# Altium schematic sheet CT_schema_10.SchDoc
size 388 x 385 mm
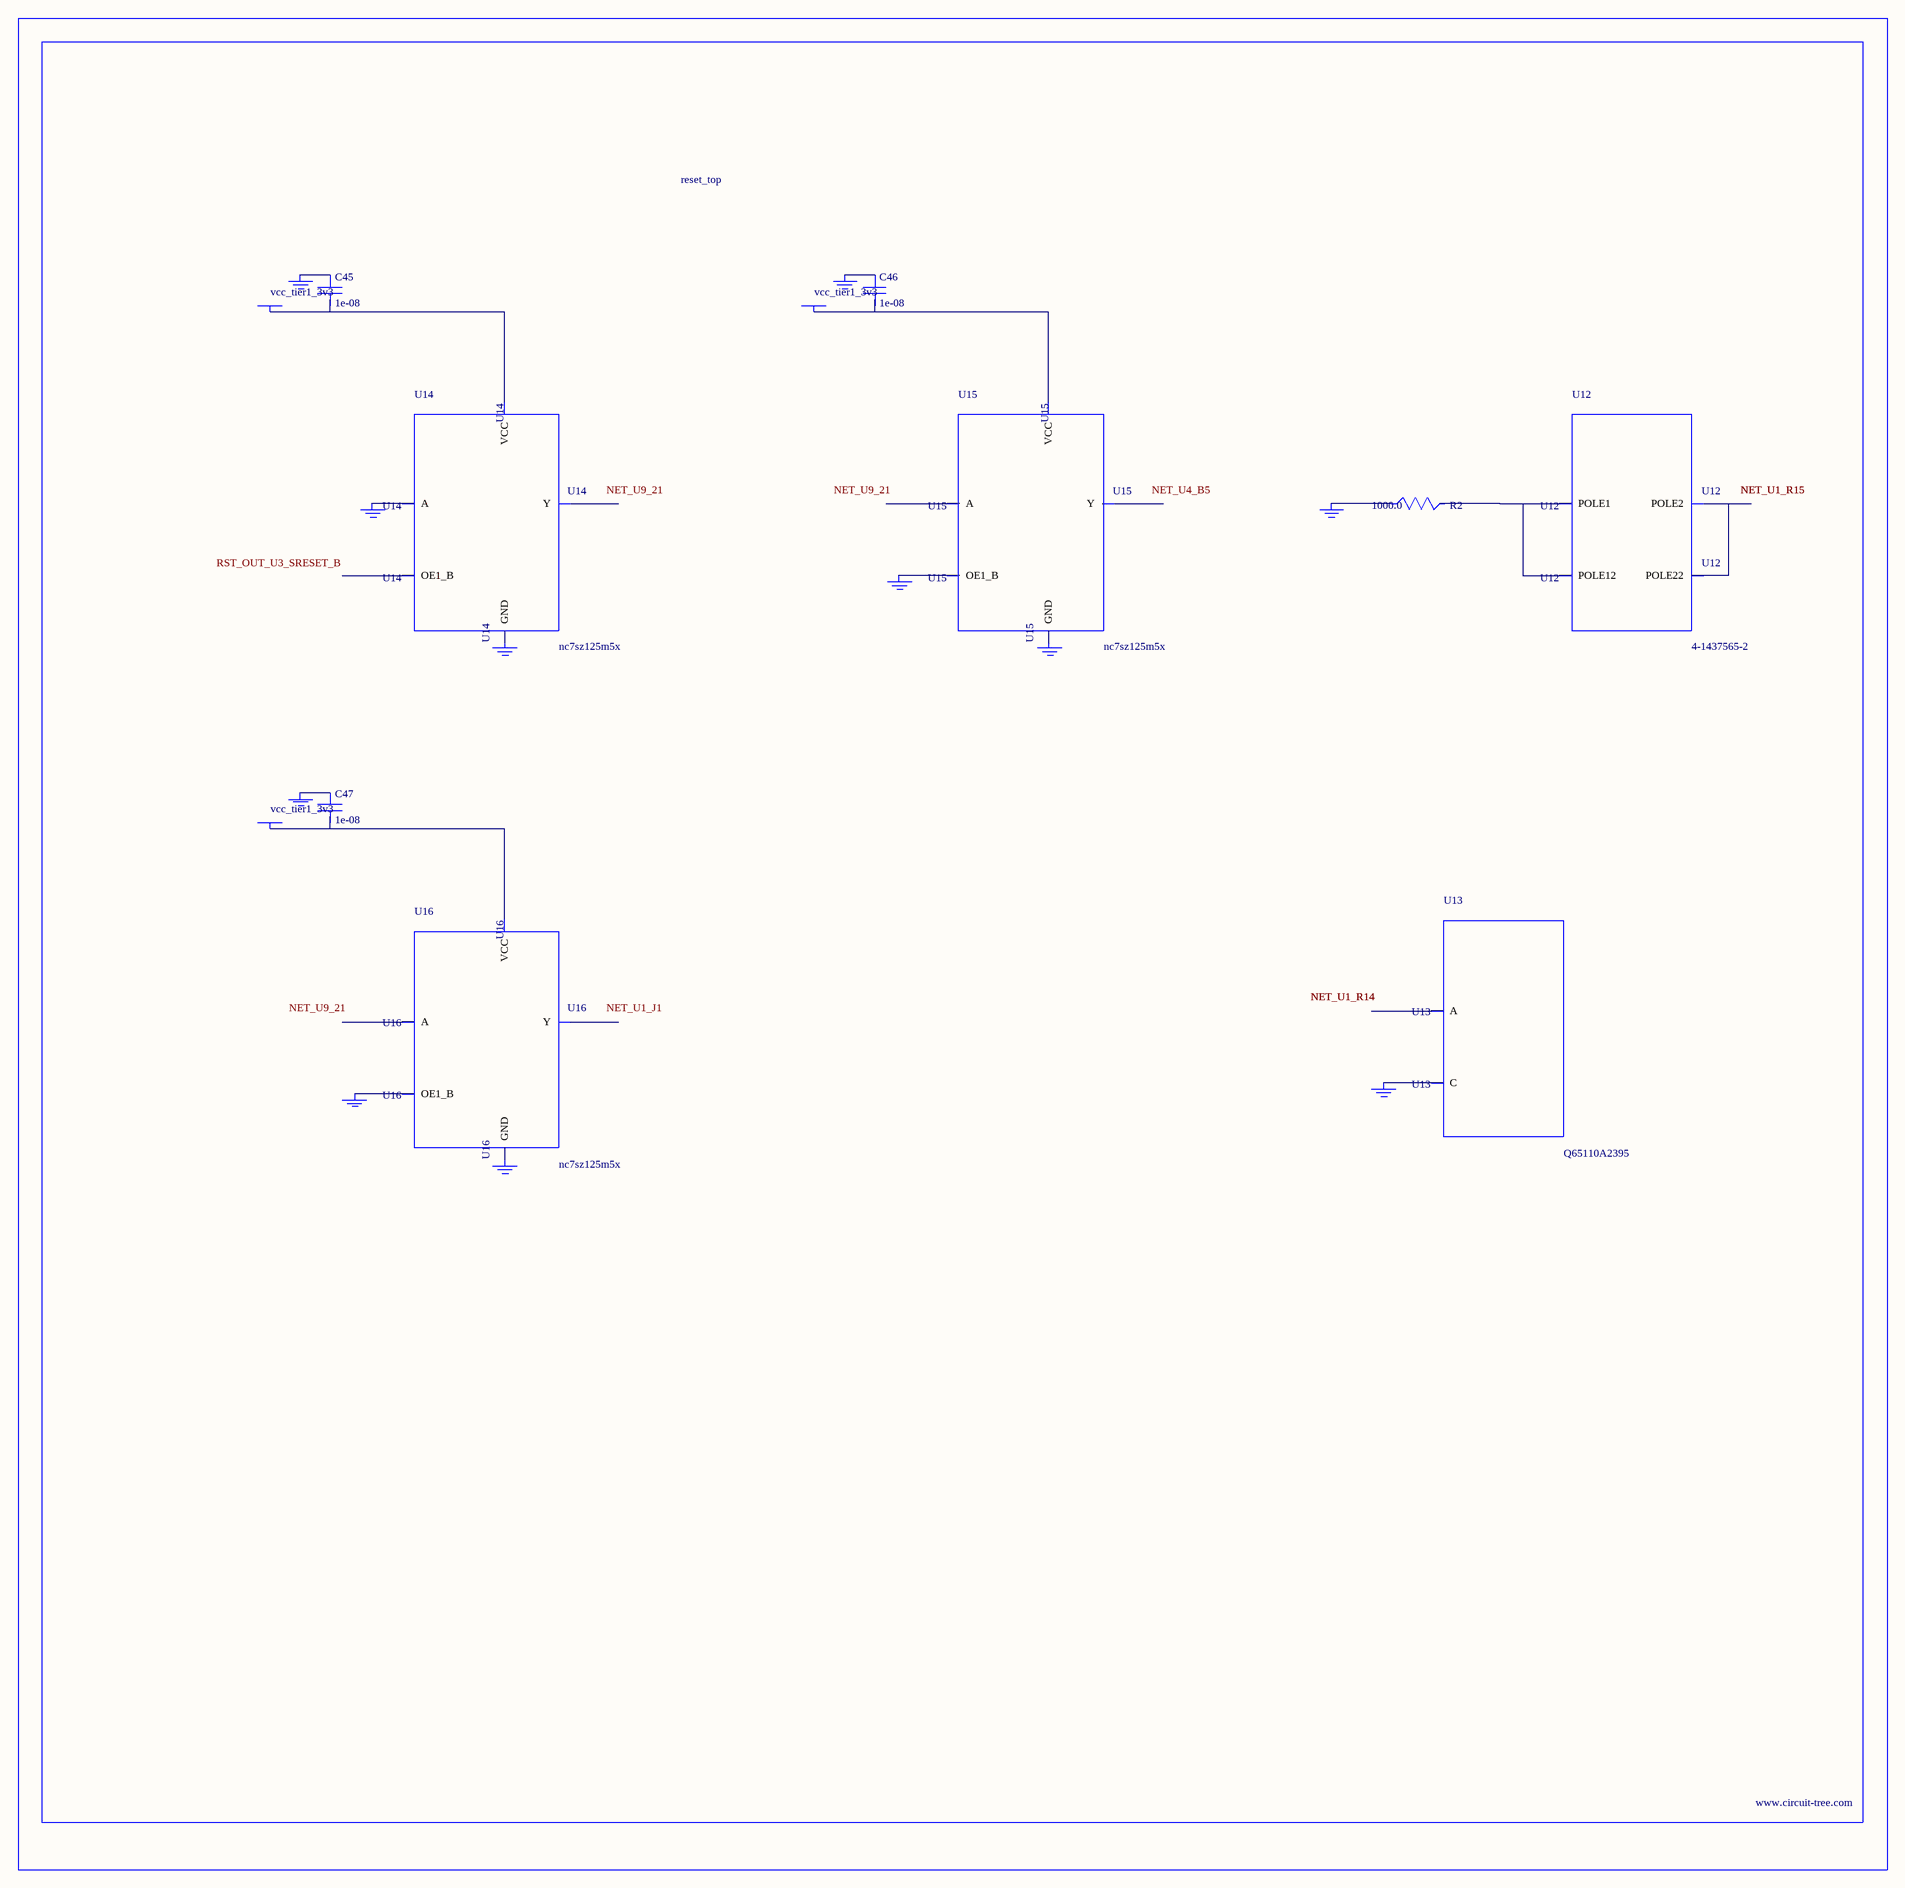
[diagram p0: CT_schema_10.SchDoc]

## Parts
BORDER9  (no value)
C45  1e-08  [C0402]
C46  1e-08  [C0402]
C47  1e-08  [C0402]
GND_INSTANCE_9_0  (no value)
GND_INSTANCE_9_1  (no value)
GND_INSTANCE_9_2  (no value)
GND_INSTANCE_9_3  (no value)
GND_INSTANCE_9_4  (no value)
GND_INSTANCE_9_5  (no value)
GND_INSTANCE_9_6  (no value)
GND_INSTANCE_9_7  (no value)
GND_INSTANCE_9_8  (no value)
GND_INSTANCE_9_9  (no value)
GND_INSTANCE_9_10  (no value)
POWER_INSTANCE_9_0  vcc_tier1_3v3
POWER_INSTANCE_9_1  vcc_tier1_3v3
POWER_INSTANCE_9_2  vcc_tier1_3v3
R2  1000.0  [R0603]
U12  4-1437565-2  [SW_4-1437565-2]
U13  Q65110A2395  [LGM67K-G1J2-24-Z]
U14  nc7sz125m5x  [NC7SZ125M5X]
U15  nc7sz125m5x  [NC7SZ125M5X]
U16  nc7sz125m5x  [NC7SZ125M5X]

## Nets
NetC45_1: C45.1 GND_INSTANCE_9_2.0(GND)
NetC45_2: C45.2 POWER_INSTANCE_9_0.0(PWR) U14.5(VCC)
NetC46_1: C46.1 GND_INSTANCE_9_5.0(GND)
NetC46_2: C46.2 POWER_INSTANCE_9_1.0(PWR) U15.5(VCC)
NetC47_1: C47.1 GND_INSTANCE_9_8.0(GND)
NetC47_2: C47.2 POWER_INSTANCE_9_2.0(PWR) U16.5(VCC)
NetGND_INSTANCE_9_0_0: GND_INSTANCE_9_0.0(GND) R2.1
NetGND_INSTANCE_9_1_0: GND_INSTANCE_9_1.0(GND) U13.C
NetGND_INSTANCE_9_3_0: GND_INSTANCE_9_3.0(GND) U14.2(A)
NetGND_INSTANCE_9_4_0: GND_INSTANCE_9_4.0(GND) U14.3(GND)
NetGND_INSTANCE_9_6_0: GND_INSTANCE_9_6.0(GND) U15.1(OE1_B)
NetGND_INSTANCE_9_7_0: GND_INSTANCE_9_7.0(GND) U15.3(GND)
NetGND_INSTANCE_9_9_0: GND_INSTANCE_9_9.0(GND) U16.1(OE1_B)
NetGND_INSTANCE_9_10_0: GND_INSTANCE_9_10.0(GND) U16.3(GND)
NetR2_2: R2.2 U12.1(POLE1) U12.2(POLE12)
NetU12_3: U12.3(POLE2) U12.4(POLE22)

Not connected (* = marked no-connect by the designer): U13 A; U14 1(OE1_B) 4(Y); U15 2(A) 4(Y); U16 2(A) 4(Y)

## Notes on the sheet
- Labels drawn without touching a wire or pin: NET_U1_J1, NET_U4_B5, NET_U9_21, RST_OUT_U3_SRESET_B

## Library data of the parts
BORDER9 = BORDER_PAGE9
C45-C47 = C0402C103K3RAC
GND_INSTANCE_9_0-GND_INSTANCE_9_10 = GND
POWER_INSTANCE_9_0-POWER_INSTANCE_9_2 = PWR
R2 = RC0603JR-071KL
